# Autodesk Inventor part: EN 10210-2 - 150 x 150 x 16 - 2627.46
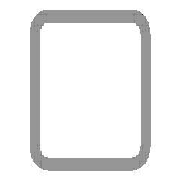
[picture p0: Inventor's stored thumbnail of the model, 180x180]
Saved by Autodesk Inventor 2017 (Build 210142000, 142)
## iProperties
Created: 2017-11
Part Number: EN 10210-2 - 150 x 150 x 16 - 2627.46
Material: Steel, Mild
Description: Tube
Document SubType Name: Modeling
Standard: DIN
Designer: iusti
Standard Revision: 2006-07
Standards Organization: DIN
Language: en-US
Size Designation: 150 x 150 x 16
Categories: <MemberInstance><Categories><Category DisplayName="Structural Shapes" InternalName="089c4875-fa83-4c05-b084-43b9cc11f5ed" Mnemonic="GRDR"><CategoryParameter Dis
Stock Number: 150 x 150 x 16
Density: 7.85 g/cm^3
Appearance: Semi-Polished
IsCustomPart: 1
_CCFamilyMember: 70
_CCFamilyDisplayName: DIN EN 10210-2 (Square) - Tube — Sizes in parentheses have been withdrawn
_FrameMemberDoc: Frame Member File
_Version: 15.0.0
_GetPNFromCC: 1
Author: iusti
G_L: 2627.460 mm
G_W: 150.000 mm
G_H: 150.000 mm
+945DE835-E5AB-4C66-A99F-F08F7F997FF3+CUTDETAIL1: Cut
+1BDD1E15-33C8-4CBC-9DCD-174E5FBEC9AD+CUTDETAIL2: Cut
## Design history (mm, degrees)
node "Start plane"
node "End plane"
sketch "Sketch"
  geometry: L1 (-75, -51)-(-75, 51); L2 (-51, 75)-(51, 75); L3 (75, 51)-(75, -51); L4 (51, -75)-(-51, -75); L5 (-43, 59)-(43, 59); L6 (59, 43)-(59, -43); L7 (43, -59)-(-43, -59); L8 (-59, -43)-(-59, 43); L9 (0, 111.959)-(0, -111.959) reference; L10 (-111.959, 0)-(111.959, 0) reference; A1 r 24 centre (-51, -51) between (-75, -51) and (-51, -75); A2 r 24 centre (-51, 51) between (-51, 75) and (-75, 51); A3 r 24 centre (51, 51) between (75, 51) and (51, 75); A4 r 24 centre (51, -51) between (51, -75) and (75, -51); A5 r 16 centre (-43, -43) between (-59, -43) and (-43, -59); A6 r 16 centre (-43, 43) between (-43, 59) and (-59, 43); A7 r 16 centre (43, 43) between (59, 43) and (43, 59); A8 r 16 centre (43, -43) between (43, -59) and (59, -43)
  constraints: 16 end point, 16 point on circle, 16 tangent, 8 centre point, 6 equal radius, 4 parallel, 2 perpendicular, 2 other
  dimensions: "d7" = 24 radius of A1 (= G_IR); "d10" = 150 distance between parallel lines of L2 L4 (= G_H); "d11" = 150 distance between parallel lines of L1 L3 (= G_W); "d12" = 16 distance between parallel lines of L3 L6 (= G_T); "d15" = 75 distance between parallel lines of L2 L10 (= 0.5 x d10); "d16" = 75 distance between parallel lines of L9 L3 (= 0.5 x d11); "d19" = 16 radius of A5 (= G_T); "d20" = 16 distance between parallel lines of L4 L7 (= G_T)
extrude "Body" new body sketch "Sketch" stored distance "d3" = 2627.46034 (= G_L); taper "d4" = 0 deg
node "Driven Length"
  sketch "Sketch3"
    geometry: L1 (0, 0)-(10, 0) reference
    constraints: 2 end point, 1 horizontal
  workplane "Work Plane3"
  sketch "Sketch4"
    geometry: L1 (-2, 35.842)-(12, 35.842) reference; L2 (-2, 2663.303)-(12, 2663.303) reference
    dimensions: "d18" = 2627.46034 distance between parallel lines of L1 L2 (derived)
workplane "Work Plane4"
split "Split1"
workplane "Work Plane5"
split "Split2"
body "Solid1"
other parameters: "G_W" = 150 [user parameter; used in 1 equation term], "G_H" = 150 [user parameter; used in 1 equation term], "G_T" = 16 [user parameter; used in 3 equation terms], "G_IR" = 24 [user parameter; used in 1 equation term], "G_L" = 2627.46034 (= d18) [user parameter; used in 1 equation term], "G_OFFSET_START" = -35.84222 [user parameter; used in 1 equation term], "G_OFFSET_END" = 92.90179 [user parameter; used in 1 equation term], "d13" = 35.84222 (= -G_OFFSET_START), "d14" = 2663.30256 (= G_OFFSET_END + B_L), "B_L" = 2570.40077 [user parameter; used in 1 equation term], "d17" = 90 deg
